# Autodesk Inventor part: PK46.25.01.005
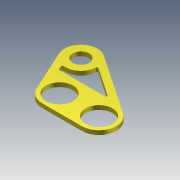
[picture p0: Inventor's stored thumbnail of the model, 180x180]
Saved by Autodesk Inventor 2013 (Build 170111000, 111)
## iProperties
Created: 2005-04
Part Number: PK46.25.01.005
Material: Steel, Mild
Document SubType Name: Modeling
Designer: salex
Manufacturer: Standard
Standards Organization: Custom
Density: 7.86 g/cm^3
Mass: 9147.22 g
Surface Area: 2089.08 cm^2
Volume: 1163.77 cm^3
Author: salex
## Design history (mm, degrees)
sketch "Эскиз1"
  geometry: L1 (-63.901, 332.782)-(298.904, 86.921); L2 (240, -105)-(0, -105); L3 (-95.464, -43.723)-(-210.918, 208.359); C1 r 82 at (0, 0); C2 r 82 at (240, 0); C3 r 50 at (-120, 250); A1 r 100 centre (-120, 250) between (-63.901, 332.782) and (-210.918, 208.359); A2 r 105 centre (0, 0) between (-95.464, -43.723) and (0, -105); A3 r 105 centre (240, 0) between (240, -105) and (298.904, 86.921)
  constraints: 6 centre point, 6 end point, 6 point on circle, 6 tangent, 3 coincident, 2 equal radius, 1 other
  dimensions: "d0" = 240 distance of C2.centre C1.centre; "d1" = 0 vertical distance of C2.centre C1.centre; "d2" = 164 diameter of C1; "d3" = 100 diameter of C3; "d4" = 105 radius of A2; "d5" = 100 radius of A1; "d6" = 250 vertical distance of C1.centre C3.centre; "d7" = 120 horizontal distance of C1.centre C3.centre
extrude "Выдавливание1" new body sketch "Эскиз1" distance "d8" = 25; taper "d9" = 0 deg
sketch "Sketch3"
  geometry: L1 (-298.904, 86.921)-(63.901, 332.782) reference; L2 (0, -105)-(-240, -105) reference; L3 (210.918, 208.359)-(95.464, -43.723) reference; L4 (-40, 78.704)-(-200, 78.704) reference; L5 (174.551, 225.016)-(59.097, -27.066); L6 (0, -65)-(-240, -65); L7 (-276.464, 53.809)-(86.341, 299.669); L8 (127.234, 121.704)-(-176.274, 121.704); C1 r 50 at (120, 250) reference; A1 r 100 centre (120, 250) between (210.918, 208.359) and (63.901, 332.782) reference; A2 r 105 centre (-240, 0) between (-298.904, 86.921) and (-240, -105) reference; A3 r 105 centre (0, 0) between (0, -105) and (95.464, -43.723) reference; A4 r 60 centre (120, 250) between (174.551, 225.016) and (86.341, 299.669); A5 r 65 centre (0, 0) between (0, -65) and (59.097, -27.066); A6 r 65 centre (-240, 0) between (-276.464, 53.809) and (-240, -65); A7 r 95 centre (120, 250) between (25.368, 258.35) and (143.881, 158.05)
  constraints: 8 end point, 8 point on circle, 4 centre point, 4 point on line, 2 parallel, 5 other
  dimensions: "d18" = 40 distance between parallel lines of L1 L7; "d19" = 45 radial gap between concentric circles of C1 A7 (computed from d18); "d20" = 43 distance between parallel lines of L8 L4 (computed from d19)
extrude "Extrusion3" cut sketch "Sketch3" stored distance "d24" = 10; taper "d25" = 0 deg
fillet "Fillet2" dims "d26" = 7
body "Solid1"
node "Reference1"
